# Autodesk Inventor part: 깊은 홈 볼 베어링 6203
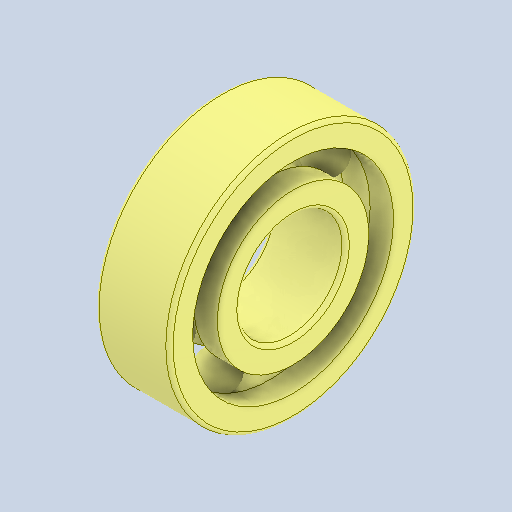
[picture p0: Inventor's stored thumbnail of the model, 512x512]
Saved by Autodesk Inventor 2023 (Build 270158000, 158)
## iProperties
Created: 2025-04
Part Number: 깊은 홈 볼 베어링 6203
Material: 강철, 연강
Description: 깊은 그루브 볼 베어링
Document SubType Name: Modeling
Designer: user
Density: 7.86 g/cm^3
Appearance: 기본값
Author: jhkim
Revision Number: 1
Sending System: Autodesk Inventor 2026
Preprocessor: ST-DEVELOPER v20.1
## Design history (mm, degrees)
feature "Solid1"
feature "Solid1:1"
feature "Solid1:2"
feature "Solid1:3"
feature "Solid1:4"
feature "Solid1:5"
feature "Solid1:6"
feature "Solid1:7"
feature "Solid1:8"
node "솔리드1"
node "솔리드2"
node "솔리드3"
node "솔리드4"
node "솔리드5"
node "솔리드6"
node "솔리드7"
node "솔리드8"
node "솔리드9"
